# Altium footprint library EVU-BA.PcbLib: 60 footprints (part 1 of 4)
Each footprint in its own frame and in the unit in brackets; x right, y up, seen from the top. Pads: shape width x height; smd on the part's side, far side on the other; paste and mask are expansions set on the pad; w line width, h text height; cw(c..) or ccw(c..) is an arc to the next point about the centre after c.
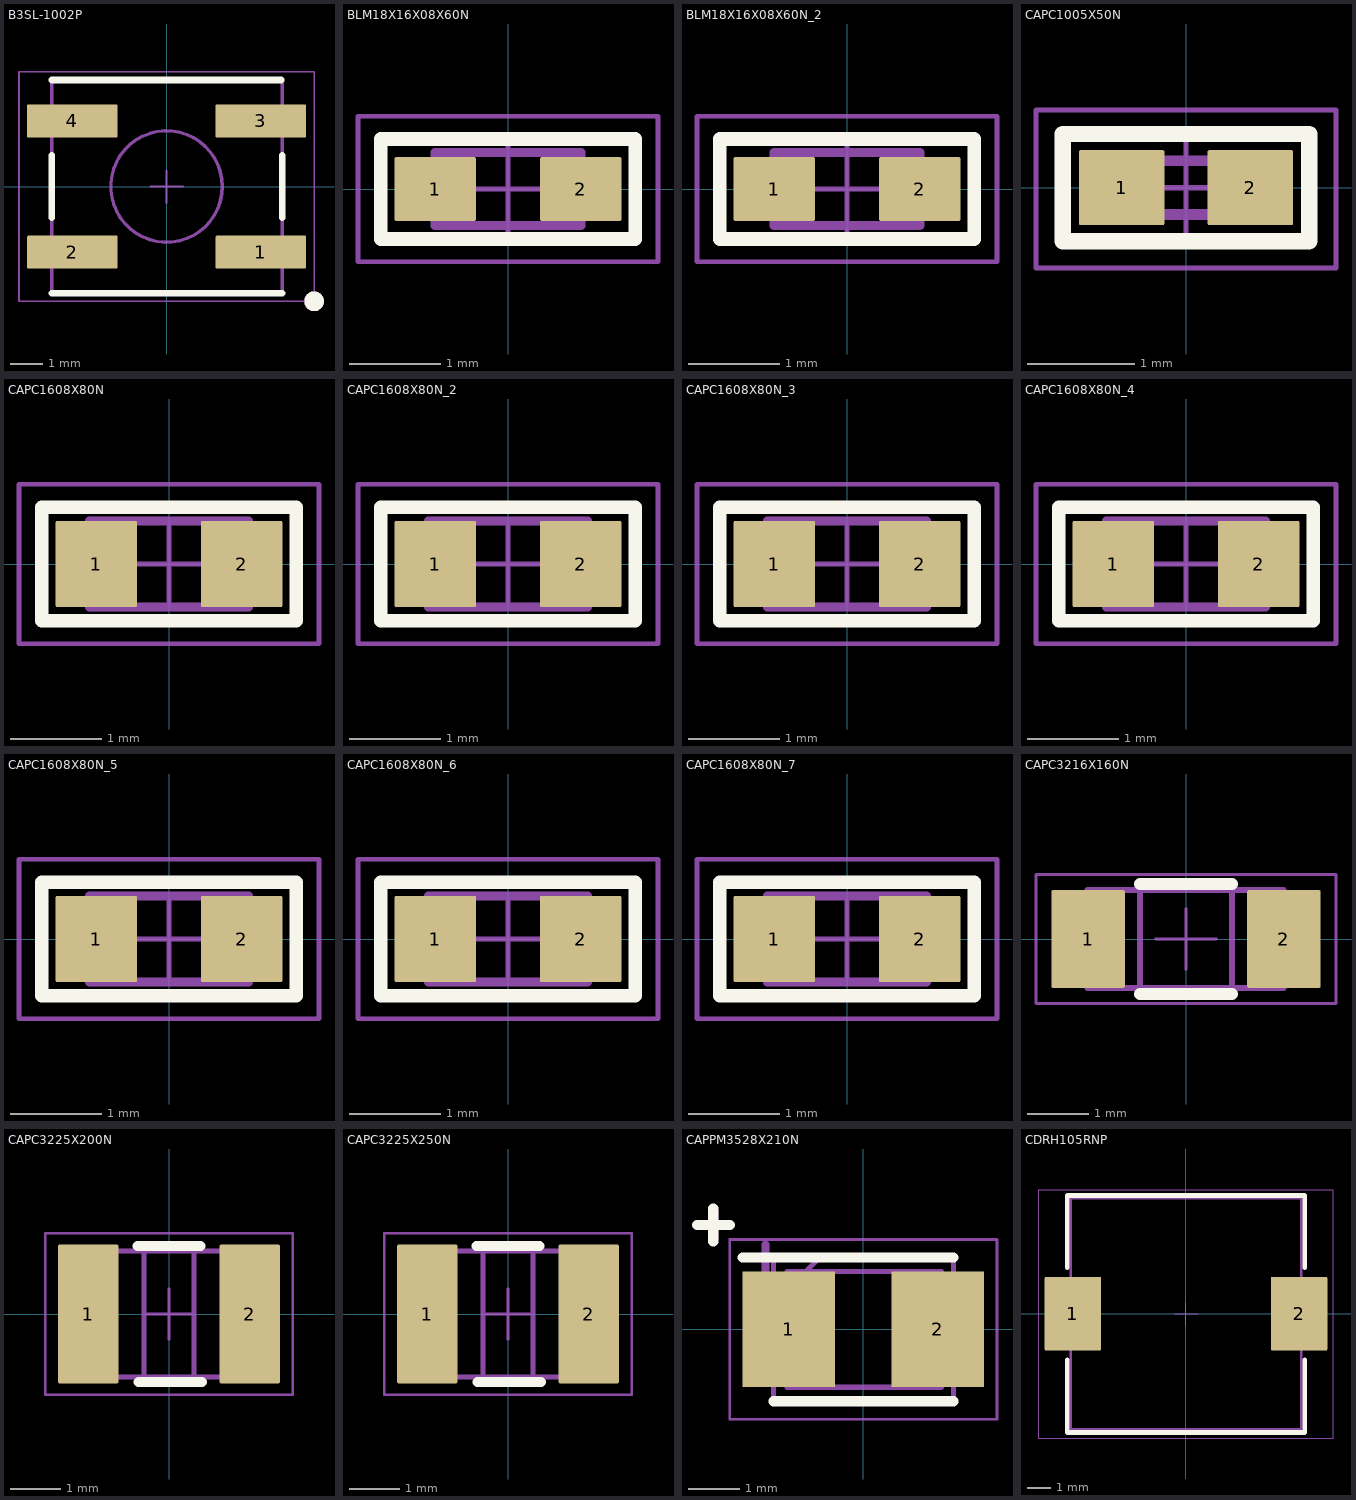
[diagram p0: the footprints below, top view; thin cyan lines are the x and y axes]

## B3SL-1002P [mm]
pads (4):
  rrect5% 2.75x1 smd mask+0.07: 1(2.875,-2) 2(-2.875,-2) 3(2.875,2) 4(-2.875,2)
Top Overlay:
  circle w0.3: c4.5,-3.5 r0.15
  lines w0.2: -3.5,-3.25 3.525,-3.25 ; -3.5,-0.95 -3.5,0.95 ; -3.5,3.25 3.5,3.25 ; 3.525,-0.95 3.525,0.95
Top Assembly:
  circle w0.3: c4.5,-3.5 r0.15
  circle w0.1: c0,0 r1.7
  lines w0.1: -3.5,-3.25 -3.5,3.25 3.525,3.25 3.525,-3.25 -3.5,-3.25
Top Designator:
  text ".Designator" at 1.026,-3.683 h1.5
Top Courtyard:
  lines w0.05: -0.5,0 0.5,0 ; 0,-0.5 0,0.5 ; -4.5,-3.5 -4.5,3.5 4.5,3.5 4.5,-3.5 -4.5,-3.5
3D body "B3SL_1002P.STEP": height 3.4, standoff 0, extent -3.5,-3.25 3.5,3.25

## BLM18X16X08X60N [mm]
pads (2):
  rrect5% 0.9x0.7 smd mask+0.07: 1(-0.8,0) 2(0.8,0)
Top Overlay:
  lines w0.15: -1.4,-0.55 -1.4,0.55 1.4,0.55 1.4,-0.55 -1.4,-0.55
Top Assembly:
  lines w0.1: -0.8,-0.4 0.8,-0.4 0.8,0.4 -0.8,0.4 -0.8,-0.4
Top Designator:
  text ".Designator" at -3.25,-0.3 h1.5
Top Courtyard:
  lines w0.05: -0.5,0 0.5,0 ; 0,-0.5 0,0.5 ; -1.65,-0.8 1.65,-0.8 1.65,0.8 -1.65,0.8 -1.65,-0.8
3D body "I0603_INDC1608X10.Step": height 1, standoff 0, extent -0.9,-0.5 0.9,0.5

## BLM18X16X08X60N_2 [mm]
pads (2):
  rrect5% 0.9x0.7 smd mask+0.07: 1(-0.8,0) 2(0.8,0)
Top Overlay:
  lines w0.15: -1.4,-0.55 1.4,-0.55 1.4,0.55 -1.4,0.55 -1.4,-0.55
Top Assembly:
  lines w0.1: -0.8,-0.4 -0.8,0.4 0.8,0.4 0.8,-0.4 -0.8,-0.4
Top Designator:
  text ".Designator" at -3.25,-0.3 h1.5
Top Courtyard:
  lines w0.05: -0.5,0 0.5,0 ; 0,-0.5 0,0.5 ; -1.65,-0.8 -1.65,0.8 1.65,0.8 1.65,-0.8 -1.65,-0.8
3D body "I0603_INDC1608X10.Step": height 1, standoff 0, extent -0.9,-0.5 0.9,0.5

## CAPC1005X50N [mm]
pads (2):
  rrect5% 0.8x0.7 smd paste-25.4 mask+0.07: 1(-0.6,0) 2(0.6,0)
Top Overlay:
  lines w0.15: -1.15,-0.5 1.15,-0.5 1.15,0.5 -1.15,0.5 -1.15,-0.5
Top Paste:
  region: -0.841,-0.241 -0.359,-0.241 -0.359,0.241 -0.841,0.241
  region: 0.359,-0.241 0.841,-0.241 0.841,0.241 0.359,0.241
Top Assembly:
  lines w0.1: -0.508,-0.25 -0.508,0.25 0.492,0.25 0.492,-0.25 -0.508,-0.25
Top Designator:
  text ".Designator" at -3.25,-0.3 h1.5
Top Courtyard:
  lines w0.05: -0.5,0 0.5,0 ; 0,-0.5 0,0.5 ; -1.4,-0.75 -1.4,0.725 1.4,0.725 1.4,-0.75 -1.4,-0.75
3D body "C0402_CAPC1005X06.Step": height 0.55, standoff 0, extent -0.525,-0.275 0.525,0.275

## CAPC1608X80N [mm]
pads (2):
  rrect5% 0.9x0.95 smd mask+0.07: 1(-0.8,0) 2(0.8,0)
Top Overlay:
  lines w0.15: -1.4,-0.625 1.4,-0.625 1.4,0.625 -1.4,0.625 -1.4,-0.625
Top Assembly:
  lines w0.1: -0.875,-0.475 0.875,-0.475 0.875,0.475 -0.875,0.475 -0.875,-0.475
Top Designator:
  text ".Designator" at -3.25,-0.3 h1.5
Top Courtyard:
  lines w0.05: -0.5,0 0.5,0 ; 0,-0.5 0,0.5 ; -1.65,-0.875 1.65,-0.875 1.65,0.875 -1.65,0.875 -1.65,-0.875
3D body "C0603_CAPC1608X09.Step": height 0.95, standoff 0, extent -0.9,-0.525 0.9,0.475

## CAPC1608X80N_2 [mm]
pads (2):
  rrect5% 0.9x0.95 smd mask+0.07: 1(-0.8,0) 2(0.8,0)
Top Overlay:
  lines w0.15: -1.4,-0.625 1.4,-0.625 1.4,0.625 -1.4,0.625 -1.4,-0.625
Top Assembly:
  lines w0.1: -0.875,-0.475 0.875,-0.475 0.875,0.475 -0.875,0.475 -0.875,-0.475
Top Designator:
  text ".Designator" at -3.25,-0.3 h1.5
Top Courtyard:
  lines w0.05: -0.5,0 0.5,0 ; 0,-0.5 0,0.5 ; -1.65,-0.875 1.65,-0.875 1.65,0.875 -1.65,0.875 -1.65,-0.875
3D body "C0603_CAPC1608X09.Step": height 0.95, standoff 0, extent -0.9,-0.525 0.9,0.475

## CAPC1608X80N_3 [mm]
pads (2):
  rrect5% 0.9x0.95 smd mask+0.07: 1(-0.8,0) 2(0.8,0)
Top Overlay:
  lines w0.15: -1.4,-0.625 1.4,-0.625 1.4,0.625 -1.4,0.625 -1.4,-0.625
Top Assembly:
  lines w0.1: -0.875,-0.475 0.875,-0.475 0.875,0.475 -0.875,0.475 -0.875,-0.475
Top Designator:
  text ".Designator" at -3.25,-0.3 h1.5
Top Courtyard:
  lines w0.05: -0.5,0 0.5,0 ; 0,-0.5 0,0.5 ; -1.65,-0.875 1.65,-0.875 1.65,0.875 -1.65,0.875 -1.65,-0.875
3D body "C0603_CAPC1608X09.Step": height 0.95, standoff 0, extent -0.9,-0.525 0.9,0.475

## CAPC1608X80N_4 [mm]
pads (2):
  rrect5% 0.9x0.95 smd mask+0.07: 1(-0.8,0) 2(0.8,0)
Top Overlay:
  lines w0.15: -1.4,-0.625 1.4,-0.625 1.4,0.625 -1.4,0.625 -1.4,-0.625
Top Assembly:
  lines w0.1: -0.875,-0.475 0.875,-0.475 0.875,0.475 -0.875,0.475 -0.875,-0.475
Top Designator:
  text ".Designator" at -3.25,-0.3 h1.5
Top Courtyard:
  lines w0.05: -0.5,0 0.5,0 ; 0,-0.5 0,0.5 ; -1.65,-0.875 1.65,-0.875 1.65,0.875 -1.65,0.875 -1.65,-0.875
3D body "C0603_CAPC1608X09.Step": height 0.95, standoff 0, extent -0.9,-0.525 0.9,0.475

## CAPC1608X80N_5 [mm]
pads (2):
  rrect5% 0.9x0.95 smd mask+0.07: 1(-0.8,0) 2(0.8,0)
Top Overlay:
  lines w0.15: -1.4,-0.625 1.4,-0.625 1.4,0.625 -1.4,0.625 -1.4,-0.625
Top Assembly:
  lines w0.1: -0.875,-0.475 0.875,-0.475 0.875,0.475 -0.875,0.475 -0.875,-0.475
Top Designator:
  text ".Designator" at -3.25,-0.3 h1.5
Top Courtyard:
  lines w0.05: -0.5,0 0.5,0 ; 0,-0.5 0,0.5 ; -1.65,-0.875 1.65,-0.875 1.65,0.875 -1.65,0.875 -1.65,-0.875
3D body "C0603_CAPC1608X09.Step": height 0.95, standoff 0, extent -0.9,-0.525 0.9,0.475

## CAPC1608X80N_6 [mm]
pads (2):
  rrect5% 0.9x0.95 smd mask+0.07: 1(-0.8,0) 2(0.8,0)
Top Overlay:
  lines w0.15: -1.4,-0.625 -1.4,0.625 1.4,0.625 1.4,-0.625 -1.4,-0.625
Top Assembly:
  lines w0.1: -0.875,-0.475 -0.875,0.475 0.875,0.475 0.875,-0.475 -0.875,-0.475
Top Designator:
  text ".Designator" at -3.25,-0.3 h1.5
Top Courtyard:
  lines w0.05: -0.5,0 0.5,0 ; 0,-0.5 0,0.5 ; -1.65,-0.875 -1.65,0.875 1.65,0.875 1.65,-0.875 -1.65,-0.875
3D body "C0603_CAPC1608X09.Step": height 0.95, standoff 0, extent -0.9,-0.525 0.9,0.475

## CAPC1608X80N_7 [mm]
pads (2):
  rrect5% 0.9x0.95 smd mask+0.07: 1(-0.8,0) 2(0.8,0)
Top Overlay:
  lines w0.15: -1.4,-0.625 1.4,-0.625 1.4,0.625 -1.4,0.625 -1.4,-0.625
Top Assembly:
  lines w0.1: -0.875,-0.475 0.875,-0.475 0.875,0.475 -0.875,0.475 -0.875,-0.475
Top Designator:
  text ".Designator" at -3.25,-0.3 h1.5
Top Courtyard:
  lines w0.05: -0.5,0 0.5,0 ; 0,-0.5 0,0.5 ; -1.65,-0.875 1.65,-0.875 1.65,0.875 -1.65,0.875 -1.65,-0.875
3D body "C0603_CAPC1608X09.Step": height 0.95, standoff 0, extent -0.9,-0.525 0.9,0.475

## CAPC3216X160N [mm]
pads (2):
  rrect5% 1.2x1.6 smd mask+0.07: 1(-1.6,0) 2(1.6,0)
Top Overlay:
  lines w0.2: -0.75,-0.9 0.75,-0.9 ; -0.75,0.9 0.75,0.9
Top Assembly:
  lines w0.1: -0.75,-0.799 -0.75,0.801 ; 0.75,-0.799 0.75,0.801 ; -1.605,-0.799 1.595,-0.799 1.595,0.801 -1.605,0.801 -1.605,-0.799
Top Designator:
  text ".Designator" at -3.25,-0.3 h1.5
Top Courtyard:
  lines w0.05: -0.5,0 0.5,0 ; 0,-0.5 0,0.5 ; -2.45,-1.05 2.45,-1.05 2.45,1.05 -2.45,1.05 -2.45,-1.05
3D body: height 1.55, standoff 0, extent -0.75,-0.75 0.75,0.75
3D body: height 1.6, standoff 0, extent -1.55,-0.8 -0.75,0.8
3D body: height 1.6, standoff 0, extent 0.75,-0.8 1.55,0.8

## CAPC3225X200N [mm]
pads (2):
  rrect5% 1.2x2.75 smd mask+0.07: 1(-1.6,0) 2(1.6,0)
Top Overlay:
  lines w0.2: -0.625,1.35 0.625,1.35 ; -0.6,-1.35 0.65,-1.35
Top Assembly:
  lines w0.1: -0.5,-1.25 -0.5,1.25 ; 0.5,-1.25 0.5,1.25 ; -1.6,-1.25 1.6,-1.25 1.6,1.25 -1.6,1.25 -1.6,-1.25
Top Designator:
  text ".Designator" at -3.25,-0.3 h1.5
Top Courtyard:
  lines w0.05: -0.5,0 0.5,0 ; 0,-0.5 0,0.5 ; -2.45,-1.6 2.45,-1.6 2.45,1.6 -2.45,1.6 -2.45,-1.6
3D body: height 2, standoff 0, extent 0.5,-1.25 1.6,1.25
3D body: height 2, standoff 0, extent -1.6,-1.25 -0.5,1.25
3D body: height 1.95, standoff 0, extent -0.5,-1.2 0.5,1.2

## CAPC3225X250N [mm]
pads (2):
  rrect5% 1.2x2.75 smd mask+0.07: 1(-1.6,0) 2(1.6,0)
Top Overlay:
  lines w0.2: -0.625,1.35 0.625,1.35 ; -0.6,-1.35 0.65,-1.35
Top Assembly:
  lines w0.1: -0.5,-1.25 -0.5,1.25 ; 0.5,-1.25 0.5,1.25 ; -1.6,-1.25 -1.6,1.25 1.6,1.25 1.6,-1.25 -1.6,-1.25
Top Designator:
  text ".Designator" at -3.25,-0.3 h1.5
Top Courtyard:
  lines w0.05: -0.5,0 0.5,0 ; 0,-0.5 0,0.5 ; -2.45,-1.6 -2.45,1.6 2.45,1.6 2.45,-1.6 -2.45,-1.6
3D body: height 2.45, standoff 0, extent -0.5,-1.2 0.5,1.2
3D body: height 2.5, standoff 0, extent -1.6,-1.25 -0.5,1.25
3D body: height 2.5, standoff 0, extent 0.5,-1.25 1.6,1.25

## CAPPM3528X210N [mm]
pads (2):
  rect 1.8x2.25 smd: 1(-1.45,0) 2(1.45,0)
Top Overlay:
  lines w0.2: -3.238,2.032 -2.603,2.032 ; -2.921,1.714 -2.921,2.349 ; -2.35,1.4 1.75,1.4 ; -1.75,-1.4 1.75,-1.4
Top Assembly:
  lines w0.1: -1.482,-1.125 1.52,-1.125 1.52,1.125 -1.482,1.125 -1.482,-1.125
  lines w0.15: -2.159,1.397 -1.651,1.397 ; -1.905,1.143 -1.905,1.651
Mechanical 12:
  lines w0.1: -1.75,0.5 -0.85,1.4 ; -1.75,-1.4 -1.75,1.4 1.75,1.4 1.75,-1.4 -1.75,-1.4
Mechanical 13:
  lines w0.2: -3.175,2.032 -2.667,2.032 ; -2.921,1.778 -2.921,2.286
Top Courtyard:
  lines w0.05: -2.6,-1.75 -2.6,1.75 2.6,1.75 2.6,-1.75 -2.6,-1.75
3D body "293D106X0020B2TE3.stp": height 2.13, standoff 0, extent -1.864,-1.539 1.87,1.535

## CDRH105RNP [mm]
pads (2):
  rrect5% 2.45x3.2 smd mask+0.07: 1(-4.9,0) 2(4.9,0)
Top Overlay:
  lines w0.2: -5.15,-2 -5.15,-5.15 5.15,-5.15 5.15,-2 ; -5.15,2 -5.15,5.125 5.15,5.125 5.15,2
Top Assembly:
  lines w0.1: -5,-5 -5,5 5,5 5,-5 -5,-5
Top Designator:
  text ".Designator" at -3.275,-0.3 h1.5
Mechanical 9:
  text ".MARK" at -1.75,0.675 h1.5
Top Courtyard:
  lines w0.05: -0.5,0 0.5,0 ; 0,-0.5 0,0.5 ; -6.375,-5.4 -6.375,5.375 6.375,5.375 6.375,-5.4 -6.375,-5.4
3D body "CDRH104R.step": height 3.78, standoff -0.06, extent -5.16,-5 5.16,5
